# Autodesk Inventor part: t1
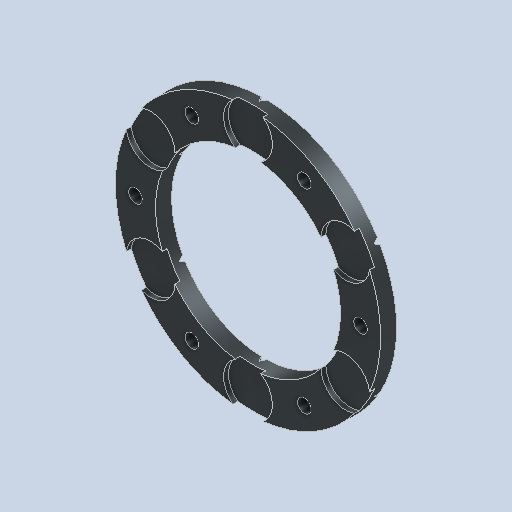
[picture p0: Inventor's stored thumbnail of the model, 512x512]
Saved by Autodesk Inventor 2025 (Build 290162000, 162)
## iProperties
Created: 2025-01
Part Number: t1
Material: Iron, Cast
Document SubType Name: Modeling
Designer: dansp
Density: 7.15 g/cm^3
Appearance: Iron Gray
Mass: 108.891 g
Surface Area: 99.9737 cm^2
Volume: 15.2295 cm^3
Author: dansp
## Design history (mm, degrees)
sketch "Sketch1"
  geometry: L1 (0, 57.75)-(0, -57.75) reference; L2 (-57.75, 0)-(57.75, 0) reference; C1 r 41.25 at (0, 0); C2 r 28.75 at (0, 0); 1 further point
  constraints: 2 centre point, 2 coincident
  dimensions: "d0" = 82.5 diameter of C1; "d1" = 12.5 radial gap between concentric circles of C1 C2
extrude "Extrusion1" new body sketch "Sketch1" distance "d2" = 5; taper "d3" = 0 deg
sketch "Sketch3" dims "d41" = 70 (= 0.5 x d40 + 0.5 x d39)
  geometry: C1 r 41.25 at (0, 0) reference; C2 r 28.75 at (0, 0) reference; C3 r 7.6 at (0, 35); 1 further point
  constraints: 2 vertical alignment, 1 centre point, 1 coincident, 2 other
  dimensions: "d39" = 82.5 diameter of C1 (derived); "d40" = 57.5 diameter of C2 (derived); "d42" = 15.2 diameter of C3
extrude "Extrusion3" cut sketch "Sketch3" distance "d16" = 1.5; taper "d17" = 0 deg
pattern_circular "Circular Pattern3" dims angle "d19" = 360 deg
sketch "Sketch5"
  geometry: L1 (-40.25, 0)-(40.25, 0) reference; L2 (0, -0.3)-(0, 1.8) reference; L3 (0.866, 0)-(0, 1.5); L4 (0, 1.5)-(-0.866, 0); L5 (-28.75, 0)-(28.75, 0) reference; 2 further points
  constraints: 4 end point, 3 point on line, 1 other
  dimensions: "d29" = 60 deg angle of L4 L3; "d30" = 1.5 distance from line of L3.end L1
extrude "Extrusion5" cut sketch "Sketch5" extent not by distance; stored distance "d31" = 0; taper "d32" = 0 deg
pattern_circular "Circular Pattern5" dims angle "d34" = 360 deg
sketch "Sketch8"
  geometry: L1 (-57.75, 0)-(57.75, 0) reference; L2 (0, -57.75)-(0, 57.75) reference; C1 r 2.1 at (35, 0); C2 r 2.1 at (-35, 0); A1 r 28.75 centre (0, 0) between (3.91, 28.483) and (-3.91, 28.483) reference; A2 r 7.6 centre (0, 35) between (-4.687, 40.983) and (-3.91, 28.483) reference; A3 r 41.25 centre (0, 0) between (4.687, 40.983) and (-4.687, 40.983) reference; A4 r 7.6 centre (0, 35) between (3.91, 28.483) and (4.687, 40.983) reference; A5 r 35 centre (0, 0) between (0, 35) and (35, 0); 1 further point
  constraints: 3 centre point, 2 point on circle, 1 coincident, 1 point on line, 1 symmetric about line, 1 other
  dimensions: "d44" = 4.2 diameter of C1
extrude "Extrusion6" cut sketch "Sketch8" extent not by distance; stored distance "d45" = 0; taper "d46" = 0 deg
pattern_circular "Circular Pattern7" dims angle "d51" = 360 deg
body "Solid1"
node "Projected Loop2"
node "Projected Loop6"
